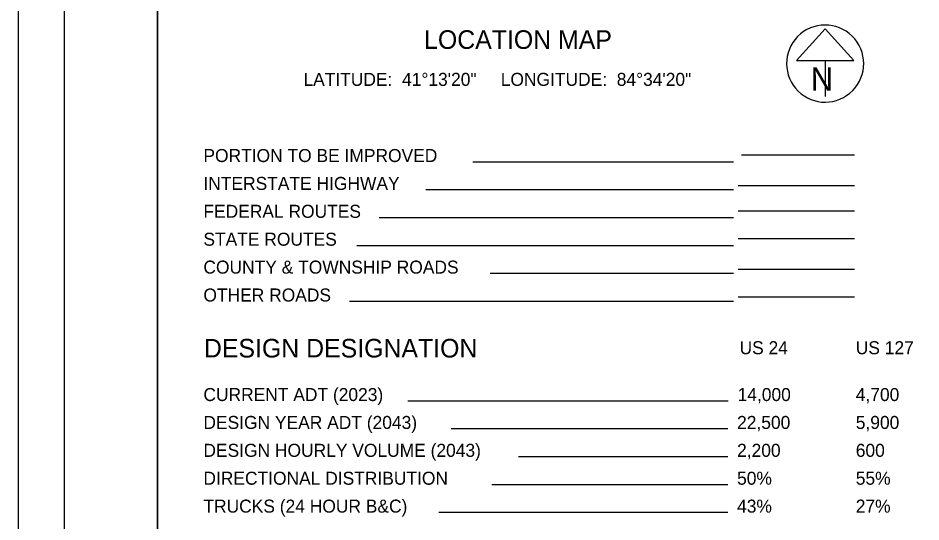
# Model space of a CAD drawing. Extents: x 0 to 64.8, y -5 to 22.
# Drawn here: x 0 to 9.72, y 8.51 to 13.93 of the extents above; entities that cross this region are included whole.
import ezdxf

# ---------------------------------------------------------------- set-up
doc = ezdxf.new("R2010")
doc.units = 0
for name, color, linetype in [('SH_Border', 7, 'Continuous'), ('SH_Cut_Line', 7, 'Continuous'), ('SH_Data', 7, 'Continuous'), ('SH_Text', 7, 'Continuous')]:
    doc.layers.add(name, color=color, linetype=linetype)

msp = doc.modelspace()

# ---------------------------------------------------------------- linework, layer by layer
at = {"layer": 'SH_Border'}
for points in [[(0.5, 21.5), (1.5, 21.5), (1.5, 0.5), (0.5, 0.5)], [(1.5, 21.5), (33.5, 21.5), (33.5, 0.5), (1.5, 0.5)]]:
    msp.add_lwpolyline(points, close=True, dxfattribs=at)
at = {"layer": 'SH_Cut_Line'}
msp.add_lwpolyline([(0, 0), (34, 0), (34, 22), (0, 22)], close=True, dxfattribs=at)
at = {"layer": 'SH_Data'}
for p, q in [((8.6845, 13.8091), (8.3769, 13.4678)), ((8.9921, 13.4678), (8.6845, 13.8091)), ((8.3769, 13.4678), (8.9921, 13.4678)), ((8.6845, 13.4678), (8.6845, 13.0811)), ((8.6845, 13.4353), (8.6845, 13.4353)), ((8.6845, 13.4353), (8.6845, 13.4353)), ((7.7827, 12.4553), (9, 12.4553)), ((7.7, 12.3767), (4.8937, 12.3767)), ((7.7, 12.0767), (4.3895, 12.0767)), ((9, 12.1207), (7.75, 12.1207)), ((7.7, 11.7767), (3.8854, 11.7767)), ((9, 11.8491), (7.75, 11.8491)), ((7.7, 11.4767), (3.6448, 11.4767)), ((9, 11.5491), (7.75, 11.5491)), ((7.7, 11.1767), (5.0782, 11.1767)), ((9, 11.2223), (7.75, 11.2223)), ((9, 10.9223), (7.75, 10.9223)), ((7.7, 10.8767), (3.5657, 10.8767)), ((7.6424, 9.8062), (4.1936, 9.8062)), ((7.6368, 9.5062), (4.6592, 9.5062)), ((7.6368, 9.2062), (5.3852, 9.2062)), ((7.6368, 8.9062), (5.0988, 8.9062)), ((7.6368, 8.6062), (4.5259, 8.6062))]:
    msp.add_line(p, q, dxfattribs=at)
msp.add_arc((8.6845, 13.4353), 0.4148, 129.77984, 129.76332, dxfattribs=at)

# ---------------------------------------------------------------- texts
for s, height, p in [('N', 0.25, (8.5292, 13.144)), ('DESIGN DESIGNATION', 0.2, (2, 10.2747))]:
    msp.add_text(s, height=height, dxfattribs=at).set_placement(p)
at = {"layer": 'SH_Text'}
for s, height, p in [('LOCATION MAP', 0.2, (4.3691, 13.5938)), ('LATITUDE:  41°13\'20"     LONGITUDE:  84°34\'20"', 0.14, (3.071, 13.1959)), ('PORTION TO BE IMPROVED', 0.14, (1.9944, 12.3767)), ('INTERSTATE HIGHWAY', 0.14, (1.9944, 12.0767)), ('FEDERAL ROUTES', 0.14, (1.9944, 11.7767)), ('STATE ROUTES', 0.14, (1.9944, 11.4767)), ('COUNTY & TOWNSHIP ROADS', 0.14, (1.9944, 11.1767)), ('OTHER ROADS', 0.14, (1.9944, 10.8767)), ('US 24', 0.14, (7.7635, 10.3098)), ('US 127', 0.14, (9.0139, 10.3098)), ('CURRENT ADT (2023)', 0.14, (1.9944, 9.8062)), ('14,000', 0.14, (7.7424, 9.8062)), ('4,700', 0.14, (9.0139, 9.8062)), ('DESIGN YEAR ADT (2043)', 0.14, (1.9944, 9.5062)), ('22,500', 0.14, (7.7368, 9.5062)), ('5,900', 0.14, (9.0139, 9.5062)), ('DESIGN HOURLY VOLUME (2043)', 0.14, (1.9944, 9.2062)), ('2,200', 0.14, (7.7368, 9.2062)), ('600', 0.14, (9.0139, 9.2062)), ('DIRECTIONAL DISTRIBUTION', 0.14, (1.9944, 8.9062)), ('50%', 0.14, (7.7368, 8.9062)), ('55%', 0.14, (9.0139, 8.9062)), ('TRUCKS (24 HOUR B&C)', 0.14, (1.9944, 8.6062)), ('43%', 0.14, (7.7368, 8.6062)), ('27%', 0.14, (9.0139, 8.6062))]:
    msp.add_text(s, height=height, dxfattribs=at).set_placement(p)

doc.saveas('drawing.dxf')
